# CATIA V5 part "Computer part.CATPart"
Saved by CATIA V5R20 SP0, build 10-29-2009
Part number: Part4
Bounding box of the stored display mesh (mm): x -35 to 11, y -125 to 125, z -100 to 0
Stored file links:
  C:\Users\HP\Downloads\Catia Project\Catia Project\Computer part.CATPart
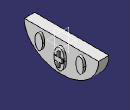
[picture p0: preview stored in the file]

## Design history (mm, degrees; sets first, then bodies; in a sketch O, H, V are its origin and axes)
Body1 (main body)
  Sketch1 on yz-plane, origin (0, 0, 0), H (0, 1, 0), V (0, 0, 1)
    ellipse A1 centre (0, 0) semi-axes 250, 100 rotation 0 from (-250, 0) to (250, 0)
    line L1 (250, 0) -> (-250, 0)
  Pad1: profile Sketch1, direction (-1, 0, 0), length 70
  Sketch2 on start face of Pad1, origin (0, 0, 0), H (0, 1, 0), V (0, 0, 1)
    circle A1 centre (137.484, -35.7689) radius 25.4646
    circle A2 centre (-137.484, -35.7689) radius 25.4646
    circle A3 centre (0, -51.4484) radius 34.0254
  Pad2: profile Sketch2, direction (1, 0, 0), length 15
  Sketch3 on end face of Pad2, origin (15, 0, 0), H (0, 1, 0), V (0, 0, 1)
    point P1 (0, -51.4739)
    line L1 (6.3405, -28.3113) -> (6.3405, -44.7493)
    line L2 (6.3405, -74.6365) -> (-6.3405, -74.6365)
    line L3 (-6.3405, -74.6365) -> (-6.3405, -58.1985)
    line L4 (-6.3405, -28.3113) -> (6.3405, -28.3113)
    line L5 (26.5567, -44.7493) -> (26.5567, -58.1985)
    line L6 (26.5567, -58.1985) -> (6.3405, -58.1985)
    line L7 (-26.5567, -58.1985) -> (-26.5567, -44.7493)
    line L8 (-26.5567, -44.7493) -> (-6.3405, -44.7493)
    line L9 (-6.3405, -58.1985) -> (-26.5567, -58.1985)
    line L10 (6.3405, -44.7493) -> (26.5567, -44.7493)
    line L11 (6.3405, -58.1985) -> (6.3405, -74.6365)
    line L12 (-6.3405, -44.7493) -> (-6.3405, -28.3113)
  Pad3: profile Sketch3, direction (1, 0, 0), length 7
  Scaling1: Reference start face of Pad1, Ratio 1, ToTransfor Pad3
  Scaling2: Reference face of Pad1 from Sketch1.L1, Ratio 1, ToTransfor Scaling1
  Scaling3: Reference end face of Pad1, Ratio 1, ToTransfor Scaling2
  Scaling4: Reference end face of Pad1, Ratio 1, ToTransfor Scaling3
  Scaling5: Reference zx-plane, Ratio 0.5, ToTransfor Scaling4
  Scaling6: Reference start face of Pad1, Ratio 0.5, ToTransfor Scaling5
